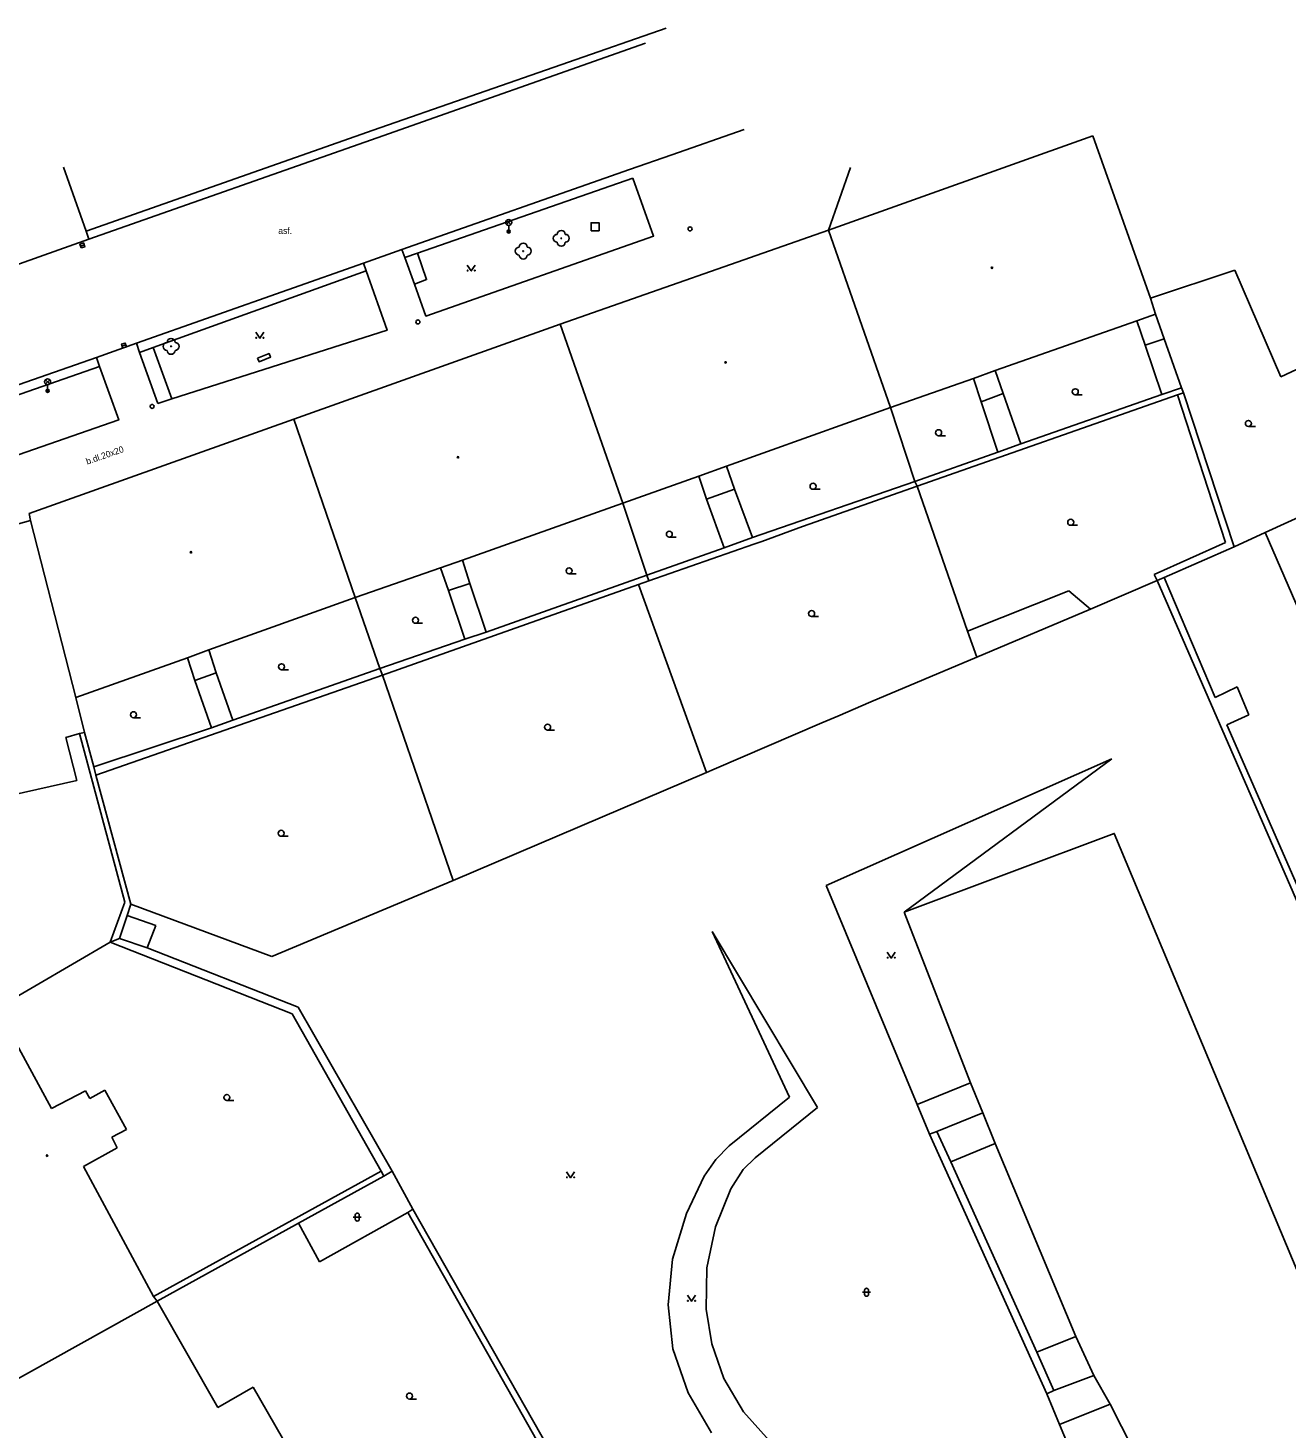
# Model space of a CAD drawing. Extents: x -599770 to -598493, y -1162076 to -1159209.
# Drawn here: x -598839.3 to -598760.3, y -1159413.9 to -1159326 of the extents above; entities that cross this region are included whole.
import ezdxf

# ---------------------------------------------------------------- set-up
doc = ezdxf.new("R2010")
doc.units = 0
doc.layers.add('Podklad', color=7, linetype='Continuous')

msp = doc.modelspace()

# ---------------------------------------------------------------- linework, layer by layer
at = {"layer": 'Podklad'}
for p, q in [((-598809.292, -1159338.38), (-598809.027, -1159338.115)), ((-598809.292, -1159338.115), (-598809.027, -1159338.38)), ((-598809.16, -1159338.435), (-598809.16, -1159338.81)), ((-598836.029, -1159339.728), (-598835.791, -1159339.652)), ((-598833.429, -1159346.008), (-598833.191, -1159345.932)), ((-598838.233, -1159348.38), (-598837.968, -1159348.115)), ((-598838.233, -1159348.115), (-598837.968, -1159348.38)), ((-598838.1, -1159348.435), (-598838.1, -1159348.81)), ((-598773.6, -1159349.058), (-598773.163, -1159349.058)), ((-598762.74, -1159351.047), (-598762.302, -1159351.047)), ((-598782.18, -1159351.628), (-598781.742, -1159351.628)), ((-598790.06, -1159354.988), (-598789.622, -1159354.988)), ((-598799.08, -1159357.997), (-598798.642, -1159357.997)), ((-598773.89, -1159357.247), (-598773.453, -1159357.247)), ((-598805.37, -1159360.297), (-598804.933, -1159360.297)), ((-598790.15, -1159362.977), (-598789.712, -1159362.977)), ((-598815.01, -1159363.398), (-598814.573, -1159363.398)), ((-598823.42, -1159366.317), (-598822.983, -1159366.317)), ((-598832.71, -1159369.328), (-598832.273, -1159369.328)), ((-598806.72, -1159370.108), (-598806.282, -1159370.108)), ((-598823.44, -1159376.767), (-598823.003, -1159376.767)), ((-598826.85, -1159393.347), (-598826.413, -1159393.347)), ((-598818.913, -1159400.668), (-598818.413, -1159400.668)), ((-598818.788, -1159400.543), (-598818.788, -1159400.793)), ((-598818.538, -1159400.543), (-598818.538, -1159400.793)), ((-598786.953, -1159405.388), (-598786.453, -1159405.388)), ((-598786.828, -1159405.263), (-598786.828, -1159405.513)), ((-598786.578, -1159405.263), (-598786.578, -1159405.513)), ((-598815.39, -1159412.087), (-598814.953, -1159412.087))]:
    msp.add_line(p, q, dxfattribs=at)
for points in [[(-598799.28, -1159326.04), (-598817.67, -1159332.45), (-598835.67, -1159338.79)], [(-598835.51, -1159339.3), (-598817.42, -1159332.93), (-598800.58, -1159327)], [(-598794.39, -1159332.41), (-598798.93, -1159334), (-598801.57, -1159334.93), (-598815.86, -1159339.94), (-598818.28, -1159340.8)], [(-598789.1, -1159338.72), (-598772.51, -1159332.81)], [(-598768.88, -1159343), (-598772.51, -1159332.81)], [(-598835.67, -1159338.79), (-598837.1, -1159334.77)], [(-598789.1, -1159338.72), (-598787.72, -1159334.79)], [(-598815.08, -1159342.11), (-598814.36, -1159344.12), (-598800.07, -1159339.1), (-598801.38, -1159335.46)], [(-598814.88, -1159340.17), (-598801.38, -1159335.46)], [(-598805.94, -1159344.62), (-598789.1, -1159338.72)], [(-598785.2, -1159349.86), (-598789.1, -1159338.72)], [(-598841.77, -1159341.51), (-598835.51, -1159339.3)], [(-598835.67, -1159338.79), (-598835.51, -1159339.3)], [(-598815.86, -1159339.94), (-598815.68, -1159340.45)], [(-598815.68, -1159340.45), (-598814.88, -1159340.17)], [(-598815.68, -1159340.45), (-598815.08, -1159342.11)], [(-598814.88, -1159340.17), (-598814.32, -1159341.83), (-598815.08, -1159342.11)], [(-598818.28, -1159340.8), (-598832.53, -1159345.83), (-598835.04, -1159346.71), (-598850.58, -1159352.14), (-598852.56, -1159352.86), (-598871.24, -1159359.39)], [(-598831.47, -1159346.09), (-598818.11, -1159341.29)], [(-598830.31, -1159349.32), (-598816.79, -1159345.01), (-598818.11, -1159341.29)], [(-598818.11, -1159341.29), (-598818.28, -1159340.8)], [(-598811.76, -1159340.915), (-598811.51, -1159341.29), (-598811.26, -1159340.915)], [(-598763.59, -1159341.23), (-598768.88, -1159343)], [(-598760.7, -1159347.94), (-598763.59, -1159341.23)], [(-598768.88, -1159343), (-598768.56, -1159343.99)], [(-598768.56, -1159343.99), (-598769.74, -1159344.41)], [(-598768.02, -1159345.54), (-598768.56, -1159343.99)], [(-598822.65, -1159350.58), (-598805.94, -1159344.62)], [(-598802, -1159355.86), (-598805.94, -1159344.62)], [(-598769.74, -1159344.41), (-598778.63, -1159347.54)], [(-598769.74, -1159344.41), (-598769.22, -1159345.95)], [(-598825.03, -1159345.135), (-598824.78, -1159345.51), (-598824.53, -1159345.135)], [(-598768.02, -1159345.54), (-598769.22, -1159345.95)], [(-598766.93, -1159348.62), (-598768.02, -1159345.54)], [(-598832.53, -1159345.83), (-598832.34, -1159346.4)], [(-598832.34, -1159346.4), (-598831.47, -1159346.09)], [(-598831.19, -1159349.6), (-598832.34, -1159346.4)], [(-598831.47, -1159346.09), (-598830.31, -1159349.32)], [(-598824.92, -1159346.77), (-598824.2, -1159346.47), (-598824.11, -1159346.69), (-598824.83, -1159346.99), (-598824.92, -1159346.77)], [(-598769.22, -1159345.95), (-598768.16, -1159349.05)], [(-598834.85, -1159347.28), (-598849.25, -1159352.31)], [(-598849.1, -1159356.01), (-598833.63, -1159350.64), (-598834.85, -1159347.28)], [(-598834.85, -1159347.28), (-598835.04, -1159346.71)], [(-598758.03, -1159346.67), (-598760.7, -1159347.94)], [(-598780, -1159348.03), (-598785.2, -1159349.86)], [(-598778.63, -1159347.54), (-598780, -1159348.03)], [(-598780, -1159348.03), (-598779.51, -1159349.51)], [(-598778.13, -1159348.98), (-598778.63, -1159347.54)], [(-598767.18, -1159349.06), (-598783.53, -1159354.8)], [(-598779.51, -1159349.51), (-598778.13, -1159348.98)], [(-598777.02, -1159352.13), (-598778.13, -1159348.98)], [(-598777.02, -1159352.13), (-598768.16, -1159349.05)], [(-598768.16, -1159349.05), (-598766.93, -1159348.62)], [(-598766.82, -1159348.93), (-598767.18, -1159349.06)], [(-598764.18, -1159358.33), (-598767.18, -1159349.06)], [(-598766.82, -1159348.93), (-598766.93, -1159348.62)], [(-598763.64, -1159358.6), (-598766.82, -1159348.93)], [(-598831.19, -1159349.6), (-598830.31, -1159349.32)], [(-598785.2, -1159349.86), (-598795.49, -1159353.54)], [(-598783.68, -1159354.5), (-598785.2, -1159349.86)], [(-598779.51, -1159349.51), (-598778.46, -1159352.66)], [(-598839.25, -1159356.51), (-598822.65, -1159350.58)], [(-598818.79, -1159361.79), (-598822.65, -1159350.58)], [(-598783.68, -1159354.5), (-598778.46, -1159352.66)], [(-598778.46, -1159352.66), (-598777.02, -1159352.13)], [(-598795.49, -1159353.54), (-598797.23, -1159354.17)], [(-598795, -1159354.98), (-598795.49, -1159353.54)], [(-598797.23, -1159354.17), (-598802, -1159355.86)], [(-598797.23, -1159354.17), (-598796.74, -1159355.61)], [(-598793.86, -1159358.02), (-598783.68, -1159354.5)], [(-598783.53, -1159354.8), (-598783.68, -1159354.5)], [(-598796.74, -1159355.61), (-598795, -1159354.98)], [(-598793.86, -1159358.02), (-598795, -1159354.98)], [(-598783.53, -1159354.8), (-598790.3, -1159357.18)], [(-598780.36, -1159363.89), (-598783.53, -1159354.8)], [(-598802, -1159355.86), (-598812.07, -1159359.43)], [(-598800.49, -1159360.38), (-598802, -1159355.86)], [(-598796.74, -1159355.61), (-598795.63, -1159358.67)], [(-598763.64, -1159358.6), (-598761.68, -1159357.7), (-598757.41, -1159355.75)], [(-598847.74, -1159359.34), (-598839.18, -1159356.94)], [(-598839.18, -1159356.94), (-598839.25, -1159356.51)], [(-598836.32, -1159368.05), (-598839.18, -1159356.94)], [(-598790.73, -1159357.33), (-598790.3, -1159357.18)], [(-598795.63, -1159358.67), (-598793.86, -1159358.02)], [(-598793.28, -1159358.26), (-598790.73, -1159357.33)], [(-598761.68, -1159357.7), (-598752.12, -1159379.73)], [(-598800.49, -1159360.38), (-598795.63, -1159358.67)], [(-598800.37, -1159360.73), (-598793.78, -1159358.44)], [(-598793.78, -1159358.44), (-598793.28, -1159358.26)], [(-598768.65, -1159360.34), (-598764.18, -1159358.33)], [(-598768.03, -1159360.52), (-598763.64, -1159358.6)], [(-598812.07, -1159359.43), (-598813.45, -1159359.92)], [(-598811.6, -1159360.9), (-598812.07, -1159359.43)], [(-598813.45, -1159359.92), (-598818.79, -1159361.79)], [(-598813.45, -1159359.92), (-598812.94, -1159361.35)], [(-598810.57, -1159363.95), (-598800.49, -1159360.38)], [(-598800.37, -1159360.73), (-598800.49, -1159360.38)], [(-598768.46, -1159360.71), (-598772.65, -1159362.51)], [(-598768.46, -1159360.71), (-598768.65, -1159360.34)], [(-598768.46, -1159360.71), (-598768.03, -1159360.52)], [(-598758.86, -1159382.74), (-598768.46, -1159360.71)], [(-598768.03, -1159360.52), (-598764.83, -1159368.06)], [(-598817.09, -1159366.65), (-598801.02, -1159360.96)], [(-598812.94, -1159361.35), (-598811.6, -1159360.9)], [(-598812.94, -1159361.35), (-598811.91, -1159364.39)], [(-598810.57, -1159363.95), (-598811.6, -1159360.9)], [(-598800.37, -1159360.73), (-598801.02, -1159360.96)], [(-598801.02, -1159360.96), (-598796.75, -1159372.77)], [(-598780.36, -1159363.89), (-598774.01, -1159361.36)], [(-598774.01, -1159361.36), (-598772.65, -1159362.51)], [(-598818.79, -1159361.79), (-598827.98, -1159365.07)], [(-598817.25, -1159366.23), (-598818.79, -1159361.79)], [(-598772.65, -1159362.51), (-598779.79, -1159365.53)], [(-598811.91, -1159364.39), (-598810.57, -1159363.95)], [(-598779.79, -1159365.53), (-598780.36, -1159363.89)], [(-598827.98, -1159365.07), (-598829.33, -1159365.56)], [(-598827.52, -1159366.5), (-598827.98, -1159365.07)], [(-598817.25, -1159366.23), (-598811.91, -1159364.39)], [(-598829.33, -1159365.56), (-598836.32, -1159368.05)], [(-598829.33, -1159365.56), (-598828.85, -1159366.99)], [(-598779.79, -1159365.53), (-598786.43, -1159368.34)], [(-598817.09, -1159366.65), (-598835.07, -1159372.93)], [(-598828.85, -1159366.99), (-598827.52, -1159366.5)], [(-598826.48, -1159369.48), (-598827.52, -1159366.5)], [(-598826.48, -1159369.48), (-598817.25, -1159366.23)], [(-598817.09, -1159366.65), (-598817.25, -1159366.23)], [(-598812.64, -1159379.54), (-598817.09, -1159366.65)], [(-598828.85, -1159366.99), (-598827.82, -1159369.97)], [(-598764.83, -1159368.06), (-598763.45, -1159367.38)], [(-598763.45, -1159367.38), (-598762.7, -1159369.15)], [(-598836.32, -1159368.05), (-598835.79, -1159370.26)], [(-598786.43, -1159368.34), (-598788.5, -1159369.22)], [(-598827.82, -1159369.97), (-598826.48, -1159369.48)], [(-598788.5, -1159369.22), (-598789.5, -1159369.65)], [(-598762.7, -1159369.15), (-598764.09, -1159369.78)], [(-598836.09, -1159370.31), (-598836.96, -1159370.57)], [(-598835.79, -1159370.26), (-598836.09, -1159370.31)], [(-598836.09, -1159370.31), (-598833.26, -1159380.9)], [(-598835.19, -1159372.42), (-598835.79, -1159370.26)], [(-598835.19, -1159372.42), (-598827.82, -1159369.97)], [(-598789.5, -1159369.65), (-598796.27, -1159372.56)], [(-598764.09, -1159369.78), (-598758.48, -1159382.58)], [(-598836.96, -1159370.57), (-598836.26, -1159373.27)], [(-598789.23, -1159379.85), (-598771.31, -1159371.91)], [(-598771.31, -1159371.91), (-598784.34, -1159381.54)], [(-598835.07, -1159372.93), (-598835.19, -1159372.42)], [(-598832.88, -1159381.03), (-598835.07, -1159372.93)], [(-598812.64, -1159379.54), (-598796.75, -1159372.77)], [(-598796.27, -1159372.56), (-598796.75, -1159372.77)], [(-598836.26, -1159373.27), (-598840.45, -1159374.21)], [(-598766.44, -1159422.23), (-598754.05, -1159417.48), (-598771.16, -1159376.59), (-598784.34, -1159381.54)], [(-598812.64, -1159379.54), (-598824.03, -1159384.32)], [(-598783.53, -1159393.6), (-598789.23, -1159379.85)], [(-598833.26, -1159380.9), (-598834.18, -1159383.42)], [(-598833.1, -1159381.75), (-598833.59, -1159383.19)], [(-598832.88, -1159381.03), (-598833.1, -1159381.75)], [(-598833.1, -1159381.75), (-598831.3, -1159382.37)], [(-598824.03, -1159384.32), (-598832.88, -1159381.03)], [(-598784.34, -1159381.54), (-598780.17, -1159392.25)], [(-598831.3, -1159382.37), (-598831.86, -1159383.77)], [(-598834.18, -1159383.42), (-598841.29, -1159387.55)], [(-598833.59, -1159383.19), (-598834.18, -1159383.42)], [(-598834.18, -1159383.42), (-598822.76, -1159387.91)], [(-598831.86, -1159383.77), (-598833.59, -1159383.19)], [(-598791.53, -1159393.15), (-598796.4, -1159382.75)], [(-598796.4, -1159382.75), (-598789.79, -1159393.79)], [(-598822.38, -1159387.5), (-598831.86, -1159383.77)], [(-598785.4, -1159384.035), (-598785.15, -1159384.41), (-598784.9, -1159384.035)], [(-598841.29, -1159387.55), (-598837.86, -1159393.85)], [(-598822.76, -1159387.91), (-598817.17, -1159397.78)], [(-598816.48, -1159397.79), (-598822.38, -1159387.5)], [(-598783.53, -1159393.6), (-598780.17, -1159392.25)], [(-598780.17, -1159392.25), (-598779.41, -1159394.13)], [(-598837.86, -1159393.85), (-598835.72, -1159392.75)], [(-598835.72, -1159392.75), (-598835.44, -1159393.22)], [(-598835.44, -1159393.22), (-598834.5, -1159392.7)], [(-598834.5, -1159392.7), (-598833.14, -1159395.17)], [(-598795.33, -1159396.19), (-598791.53, -1159393.15)], [(-598789.79, -1159393.79), (-598793.69, -1159396.95)], [(-598782.75, -1159395.47), (-598783.53, -1159393.6)], [(-598779.41, -1159394.13), (-598782.3, -1159395.29)], [(-598779.41, -1159394.13), (-598778.64, -1159396.05)], [(-598833.14, -1159395.17), (-598834.07, -1159395.65)], [(-598834.07, -1159395.65), (-598833.73, -1159396.32)], [(-598782.3, -1159395.29), (-598782.75, -1159395.47)], [(-598775.38, -1159411.76), (-598782.75, -1159395.47)], [(-598782.3, -1159395.29), (-598781.42, -1159397.2)], [(-598833.73, -1159396.32), (-598835.85, -1159397.49)], [(-598796.17, -1159397.05), (-598795.33, -1159396.19)], [(-598778.64, -1159396.05), (-598781.42, -1159397.2)], [(-598778.64, -1159396.05), (-598773.57, -1159408.16)], [(-598835.85, -1159397.49), (-598831.45, -1159405.66)], [(-598796.9, -1159398.1), (-598796.17, -1159397.05)], [(-598793.69, -1159396.95), (-598794.44, -1159397.69)], [(-598781.42, -1159397.2), (-598776.02, -1159409.15)], [(-598817.17, -1159397.78), (-598831.45, -1159405.66)], [(-598816.99, -1159398.09), (-598822.35, -1159401.04)], [(-598817.17, -1159397.78), (-598816.99, -1159398.09)], [(-598816.48, -1159397.79), (-598816.99, -1159398.09)], [(-598815.18, -1159400.17), (-598816.48, -1159397.79)], [(-598805.53, -1159397.825), (-598805.28, -1159398.2), (-598805.03, -1159397.825)], [(-598798, -1159400.45), (-598796.9, -1159398.1)], [(-598794.44, -1159397.69), (-598795.21, -1159398.89)], [(-598795.21, -1159398.89), (-598796.18, -1159401.27)], [(-598815.18, -1159400.17), (-598815.5, -1159400.38)], [(-598806.1, -1159416.15), (-598815.18, -1159400.17)], [(-598822.35, -1159401.04), (-598831.23, -1159405.95)], [(-598821.04, -1159403.48), (-598822.35, -1159401.04)], [(-598815.5, -1159400.38), (-598821.04, -1159403.48)], [(-598815.5, -1159400.38), (-598806.44, -1159416.38)], [(-598798.88, -1159403.31), (-598798, -1159400.45)], [(-598796.18, -1159401.27), (-598796.73, -1159403.85)], [(-598799.16, -1159406.18), (-598798.88, -1159403.31)], [(-598796.73, -1159403.85), (-598796.76, -1159406.44)], [(-598831.23, -1159405.95), (-598842.63, -1159412.29)], [(-598831.45, -1159405.66), (-598831.23, -1159405.95)], [(-598831.23, -1159405.95), (-598827.42, -1159412.61)], [(-598798.85, -1159408.94), (-598799.16, -1159406.18)], [(-598797.94, -1159405.575), (-598797.69, -1159405.95), (-598797.44, -1159405.575)], [(-598796.76, -1159406.44), (-598796.41, -1159408.63)], [(-598776.02, -1159409.15), (-598773.57, -1159408.16)], [(-598773.57, -1159408.16), (-598772.43, -1159410.61)], [(-598797.9, -1159411.7), (-598798.85, -1159408.94)], [(-598796.41, -1159408.63), (-598795.66, -1159410.79)], [(-598776.02, -1159409.15), (-598774.95, -1159411.56)], [(-598795.66, -1159410.79), (-598794.43, -1159412.9)], [(-598774.95, -1159411.56), (-598772.43, -1159410.61)], [(-598772.43, -1159410.61), (-598771.42, -1159412.41)], [(-598827.42, -1159412.61), (-598825.19, -1159411.35)], [(-598825.19, -1159411.35), (-598823.35, -1159414.55)], [(-598775.38, -1159411.76), (-598774.95, -1159411.56)], [(-598796.44, -1159414.2), (-598797.9, -1159411.7)], [(-598774.59, -1159413.68), (-598775.38, -1159411.76)], [(-598771.42, -1159412.41), (-598774.59, -1159413.68)], [(-598771.42, -1159412.41), (-598766.44, -1159422.23)], [(-598794.43, -1159412.9), (-598792.79, -1159414.71)], [(-598768.86, -1159427.37), (-598774.59, -1159413.68)]]:
    msp.add_lwpolyline(points, dxfattribs=at)
for points in [[(-598803.99, -1159338.76), (-598803.49, -1159338.76), (-598803.49, -1159338.26), (-598803.99, -1159338.26)], [(-598835.99, -1159339.847), (-598835.753, -1159339.771), (-598835.829, -1159339.533), (-598836.067, -1159339.609)], [(-598833.391, -1159346.127), (-598833.153, -1159346.05), (-598833.229, -1159345.813), (-598833.467, -1159345.889)]]:
    msp.add_lwpolyline(points, close=True, dxfattribs=at)
for centre, radius in [((-598809.16, -1159338.247), 0.188), ((-598809.16, -1159338.81), 0.1), ((-598809.16, -1159338.81), 0.0723), ((-598797.78, -1159338.65), 0.125), ((-598809.16, -1159338.81), 0.0438), ((-598805.86, -1159339.24), 0.025), ((-598808.25, -1159340.04), 0.025), ((-598811.735, -1159341.265), 0.025), ((-598811.285, -1159341.265), 0.025), ((-598778.83, -1159341.09), 0.045), ((-598778.83, -1159341.09), 0.0199), ((-598814.86, -1159344.49), 0.125), ((-598825.005, -1159345.485), 0.025), ((-598824.555, -1159345.485), 0.025), ((-598830.35, -1159346.02), 0.025), ((-598795.55, -1159347.03), 0.045), ((-598795.55, -1159347.03), 0.0199), ((-598838.1, -1159348.247), 0.188), ((-598838.1, -1159348.81), 0.1), ((-598838.1, -1159348.81), 0.0723), ((-598838.1, -1159348.81), 0.0438), ((-598773.6, -1159348.87), 0.188), ((-598831.54, -1159349.79), 0.125), ((-598762.74, -1159350.86), 0.188), ((-598782.18, -1159351.44), 0.188), ((-598812.34, -1159352.98), 0.045), ((-598812.34, -1159352.98), 0.0199), ((-598790.06, -1159354.8), 0.188), ((-598773.89, -1159357.06), 0.188), ((-598799.08, -1159357.81), 0.188), ((-598829.1, -1159358.94), 0.045), ((-598829.1, -1159358.94), 0.0199), ((-598805.37, -1159360.11), 0.188), ((-598815.01, -1159363.21), 0.188), ((-598790.15, -1159362.79), 0.188), ((-598823.42, -1159366.13), 0.188), ((-598832.71, -1159369.14), 0.188), ((-598806.72, -1159369.92), 0.188), ((-598823.44, -1159376.58), 0.188), ((-598785.375, -1159384.385), 0.025), ((-598784.925, -1159384.385), 0.025), ((-598826.85, -1159393.16), 0.188), ((-598838.13, -1159396.81), 0.045), ((-598838.13, -1159396.81), 0.0199), ((-598805.505, -1159398.175), 0.025), ((-598805.055, -1159398.175), 0.025), ((-598797.915, -1159405.925), 0.025), ((-598797.465, -1159405.925), 0.025), ((-598815.39, -1159411.9), 0.188)]:
    msp.add_circle(centre, radius, dxfattribs=at)
for centre, radius, start, end in [((-598805.86, -1159338.99), 0.25, 0, 180), ((-598808.25, -1159339.79), 0.25, 0, 180), ((-598806.11, -1159339.24), 0.25, 90, 270), ((-598805.86, -1159339.49), 0.25, 180, 0), ((-598805.61, -1159339.24), 0.25, 270, 90), ((-598808.5, -1159340.04), 0.25, 90, 270), ((-598808.25, -1159340.29), 0.25, 180, 0), ((-598808, -1159340.04), 0.25, 270, 90), ((-598830.6, -1159346.02), 0.25, 90, 270), ((-598830.35, -1159345.77), 0.25, 0, 180), ((-598830.1, -1159346.02), 0.25, 270, 90), ((-598830.35, -1159346.27), 0.25, 180, 0), ((-598818.663, -1159400.543), 0.125, 0, 180), ((-598818.663, -1159400.793), 0.125, 180, 0), ((-598786.703, -1159405.263), 0.125, 0, 180), ((-598786.703, -1159405.513), 0.125, 180, 0)]:
    msp.add_arc(centre, radius, start, end, dxfattribs=at)

# ---------------------------------------------------------------- texts
msp.add_text('asf.', height=0.4, dxfattribs=at).set_placement((-598823.62, -1159338.96))
msp.add_text('b.dl.20x20', height=0.4, rotation=19.23, dxfattribs=at).set_placement((-598835.61, -1159353.45))

doc.saveas('drawing.dxf')
